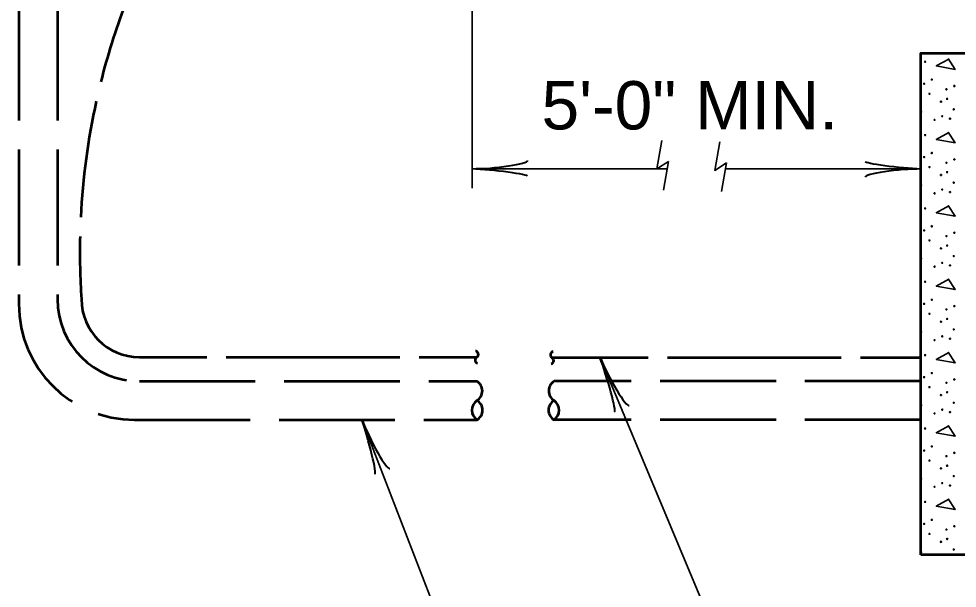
# Model space of a CAD drawing. Extents: x -1 to 679, y 0 to 440.
# Drawn here: x 342.74 to 391.38, y 76.89 to 106.38 of the extents above; entities that cross this region are included whole.
import ezdxf
from ezdxf.enums import TextEntityAlignment as Align

# ---------------------------------------------------------------- set-up
doc = ezdxf.new("R2010")
doc.units = 0
doc.linetypes.add('LONG_DASHED', pattern=[7.5, 6, -1.5])
doc.layers.add('1', color=7, linetype='Continuous', lineweight=35)

msp = doc.modelspace()

# ---------------------------------------------------------------- linework, layer by layer
at = {"layer": '1', "linetype": 'LONG_DASHED', "lineweight": 53}
for p, q in [((342.736, 129.608), (342.736, 91.608)), ((344.736, 129.608), (344.736, 91.858)), ((348.986, 87.608), (366.486, 87.608)), ((389.486, 87.608), (370.486, 87.608)), ((348.736, 85.608), (366.486, 85.608)), ((389.486, 85.608), (370.486, 85.608))]:
    msp.add_line(p, q, dxfattribs=at)
at = {"layer": '1'}
for p, q in [((366.236, 122.608), (366.236, 97.608)), ((376.061, 100.084), (375.8, 98.606)), ((375.8, 98.606), (376.419, 98.989)), ((376.419, 98.989), (376.159, 97.512)), ((379.426, 98.912), (379.165, 97.435)), ((366.236, 98.608), (376.361, 98.608)), ((379.361, 98.608), (389.486, 98.608)), ((372.863, 88.827), (381.229, 68.89)), ((360.525, 85.608), (372.352, 55.053))]:
    msp.add_line(p, q, dxfattribs=at)
at = {"layer": '1', "lineweight": 53}
for p, q in [((348.986, 88.858), (352.486, 88.858)), ((353.486, 88.858), (362.486, 88.858)), ((363.486, 88.858), (366.486, 88.858)), ((375.363, 88.827), (370.363, 88.827)), ((385.363, 88.827), (376.363, 88.827)), ((389.486, 88.827), (386.363, 88.827))]:
    msp.add_line(p, q, dxfattribs=at)
msp.add_lwpolyline([(389.486, 78.608), (389.486, 104.608), (415.486, 104.608), (415.486, 78.608)], close=True, dxfattribs=at)
at = {"layer": '1'}
for points in [[(390.95, 104.296), (390.29, 103.936), (391.27, 103.756), (390.91, 104.316)], [(390.95, 100.496), (390.29, 100.136), (391.27, 99.956), (390.91, 100.516)], [(379.067, 100.006), (378.807, 98.529), (379.426, 98.912)], [(390.95, 96.696), (390.29, 96.336), (391.27, 96.156), (390.91, 96.716)], [(390.95, 92.896), (390.29, 92.536), (391.27, 92.356), (390.91, 92.916)], [(390.95, 89.096), (390.29, 88.736), (391.27, 88.556), (390.91, 89.116)], [(390.95, 85.296), (390.29, 84.936), (391.27, 84.756), (390.91, 85.316)], [(390.95, 81.496), (390.29, 81.136), (391.27, 80.956), (390.91, 81.516)]]:
    msp.add_lwpolyline(points, dxfattribs=at)
for centre in [(389.716, 104.158), (390.061, 103.229), (389.663, 103.017), (390.816, 102.726), (391.227, 102.898), (389.941, 102.5), (390.856, 102.235), (390.538, 102.089), (391.2, 101.692), (390.604, 101.334), (391.002, 101.206), (390.206, 101.14), (389.716, 100.358), (389.663, 99.217), (390.061, 99.429), (390.816, 98.926), (391.227, 99.098), (389.941, 98.7), (390.538, 98.289), (390.856, 98.435), (391.2, 97.892), (390.206, 97.34), (390.604, 97.534), (391.002, 97.406), (389.716, 96.558), (389.663, 95.417), (390.061, 95.629), (389.941, 94.9), (390.816, 95.126), (391.227, 95.298), (390.538, 94.489), (390.856, 94.635), (391.2, 94.092), (390.206, 93.54), (390.604, 93.734), (391.002, 93.606), (389.716, 92.758), (389.663, 91.617), (390.061, 91.829), (391.227, 91.498), (389.941, 91.1), (390.816, 91.326), (390.538, 90.689), (390.856, 90.835), (391.2, 90.292), (390.206, 89.74), (390.604, 89.934), (391.002, 89.806), (389.716, 88.958), (390.061, 88.029), (389.663, 87.817), (391.227, 87.698), (389.941, 87.3), (390.816, 87.526), (390.538, 86.889), (390.856, 87.035), (390.604, 86.134), (391.2, 86.492), (390.206, 85.94), (391.002, 86.006), (389.716, 85.158), (390.061, 84.229), (389.663, 84.017), (390.816, 83.726), (391.227, 83.898), (389.941, 83.5), (390.856, 83.235), (390.538, 83.089), (391.2, 82.692), (390.604, 82.334), (391.002, 82.206), (390.206, 82.14), (389.716, 81.358), (390.061, 80.429), (389.663, 80.217), (390.816, 79.926), (391.227, 80.098), (389.941, 79.7), (390.538, 79.289), (390.856, 79.435), (391.2, 78.892)]:
    msp.add_circle(centre, 0.0265, dxfattribs=at)
at = {"layer": '1', "lineweight": 53}
for centre, radius, start, end in [((382.177, 94.31), 36.274, 159.3392, 165.9622), ((382.177, 94.31), 36.274, 167.5848, 177.1578), ((382.177, 94.31), 36.274, 178.7384, 183.8749), ((348.986, 91.858), 3, 180, 270), ((366.388, 89), 0.172, 304.5563, 83.6232), ((370.461, 88.969), 0.172, 96.3768, 235.4437), ((366.558, 88.701), 0.172, 114.6193, 253.6863), ((370.291, 88.67), 0.172, 286.3137, 65.3807), ((366.178, 87.108), 0.587, 301.6319, 58.3681), ((370.794, 87.108), 0.587, 121.6319, 238.3681), ((366.833, 86.108), 0.609, 124.7655, 235.2345), ((366.204, 86.108), 0.574, 299.3912, 60.6088), ((370.767, 86.108), 0.574, 119.3912, 240.6088), ((370.139, 86.108), 0.609, 304.7655, 55.2345)]:
    msp.add_arc(centre, radius, start, end, dxfattribs=at)
at = {"layer": '1'}
for centre in [(389.504, 101.559), (389.504, 97.759), (389.504, 93.959), (389.504, 90.159), (389.504, 86.359), (389.504, 82.559), (389.504, 78.759)]:
    msp.add_arc(centre, 0.0265, 226.4481, 133.5519, dxfattribs=at)
at = {"layer": '1', "linetype": 'LONG_DASHED', "lineweight": 53}
for centre, radius in [((348.736, 91.608), 6), ((348.986, 91.858), 4.25)]:
    msp.add_arc(centre, radius, 180, 270, dxfattribs=at)
at = {"layer": '1', "lineweight": 40}
for centre, major_axis, ratio, start_param, end_param in [((367.327, 98.885), (-1.786, -0.156), 0.122415, 0.896353, 3.141593), ((367.327, 98.885), (-1.786, -0.156), 0.122415, 0.896353, 3.141593), ((388.365, 98.82), (1.756, -0.176), 0.07063, 3.140715, 5.41811), ((388.365, 98.82), (1.756, -0.176), 0.07063, 3.140715, 5.41811), ((367.356, 98.397), (-1.756, 0.176), 0.07063, 3.140715, 5.41811), ((367.356, 98.397), (-1.756, 0.176), 0.07063, 3.140715, 5.41811), ((388.395, 98.332), (1.786, 0.156), 0.122415, 0.896353, 3.141593), ((388.395, 98.332), (1.786, 0.156), 0.122415, 0.896353, 3.141593), ((373.102, 87.712), (0.518, -1.688), 0.07063, 6.282307, 8.559703), ((373.102, 87.712), (0.518, -1.688), 0.07063, 6.282307, 8.559703), ((373.54, 87.928), (-0.835, 1.586), 0.122415, 0.896353, 3.141593), ((373.54, 87.928), (-0.835, 1.586), 0.122415, 0.896353, 3.141593), ((360.732, 84.487), (-0.47, 1.701), 0.07063, 3.140715, 5.41811), ((361.176, 84.69), (-0.79, 1.609), 0.122415, 0.896353, 3.141593)]:
    msp.add_ellipse(centre, major_axis=major_axis, ratio=ratio, start_param=start_param, end_param=end_param, dxfattribs=at)

# ---------------------------------------------------------------- texts
at = {"layer": '1', "width": 1.05}
msp.add_text('5\'-0" MIN.', height=2.5, dxfattribs=at).set_placement((377.516, 100.65), align=Align.CENTER)

doc.saveas('drawing.dxf')
